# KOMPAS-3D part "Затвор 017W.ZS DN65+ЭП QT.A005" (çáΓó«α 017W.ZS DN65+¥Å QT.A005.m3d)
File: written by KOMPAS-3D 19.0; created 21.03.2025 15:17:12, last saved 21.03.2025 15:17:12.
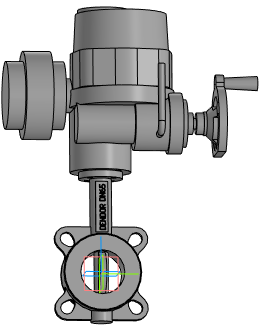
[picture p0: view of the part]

Document properties: Полное имя файла: Затвор 017W.ZS DN65+ЭП QT.A005.a3d

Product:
- Part/product: Затвор 017W.ZS DN65+ЭП QT.A005
    Масса: 39.8855

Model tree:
1. Операция без истории:1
